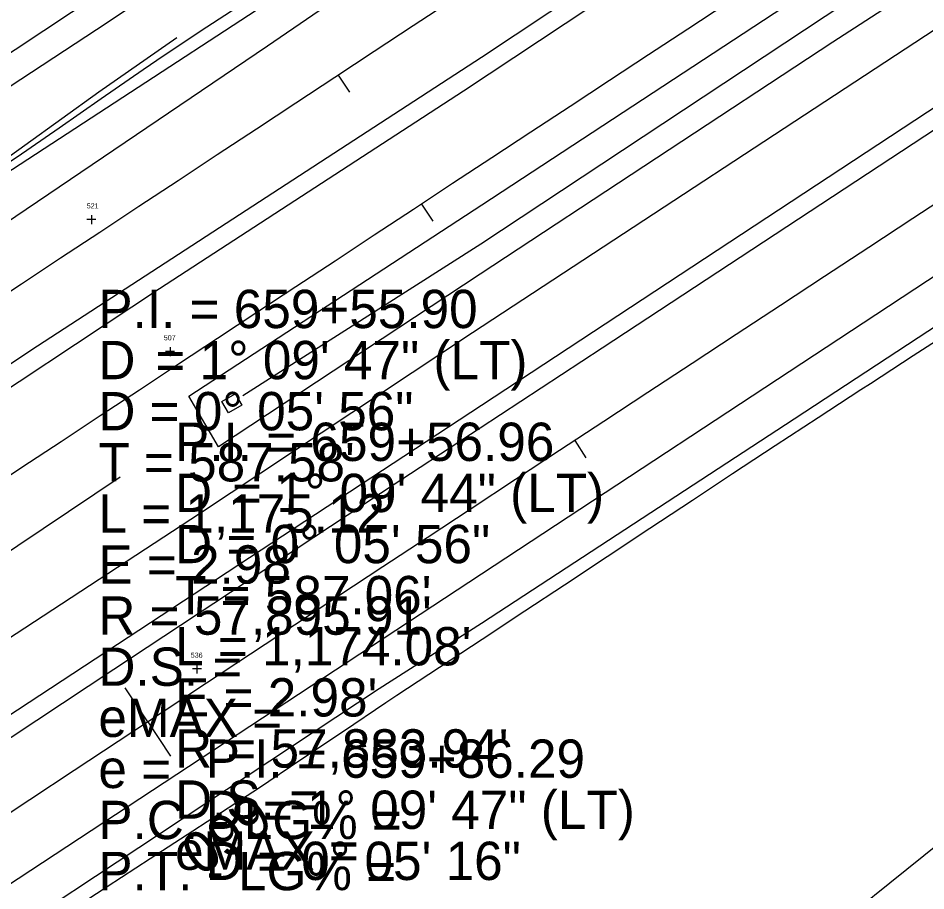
# Model space of a CAD drawing. Extents: x 1901471 to 1963503, y 756461 to 799997.
# Drawn here: x 1916709.3 to 1916886.8, y 764904.9 to 765075.7 of the extents above; entities that cross this region are included whole.
import ezdxf

# ---------------------------------------------------------------- set-up
doc = ezdxf.new("R2010")
doc.units = 0
for name, color, linetype in [('Default', 7, 'Continuous'), ('RD_DTM_BkLn1', 7, 'Continuous'), ('RD_EX_DR_ErosCtrl', 7, 'Continuous'), ('RD_EX_DR_Inlet', 7, 'Continuous'), ('RD_EX_Fence_Other', 7, 'Continuous'), ('RD_EX_GuardRail', 7, 'Continuous'), ('RD_EX_H2O', 7, 'Continuous'), ('RD_EX_Road', 7, 'Continuous'), ('RD_EX_VEG', 7, 'Continuous'), ('RD_HC_Cl', 7, 'Continuous'), ('RD_HC_Data', 7, 'Continuous'), ('RD_HC_Data_Tic', 7, 'Continuous'), ('RD_HC_TX_Sta50', 7, 'Continuous')]:
    doc.layers.add(name, color=color, linetype=linetype)

msp = doc.modelspace()

# ---------------------------------------------------------------- linework, layer by layer
at = {"layer": 'Default'}
for p, q in [((1916723.6276000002, 765037.0992000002), (1916723.6276000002, 765035.3492000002)), ((1916724.5026000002, 765036.2242000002), (1916722.7526000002, 765036.2242000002)), ((1916739.9036000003, 765010.4105000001), (1916738.1536000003, 765010.4105000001)), ((1916739.0286000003, 765011.2855000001), (1916739.0286000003, 765009.5355000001)), ((1916745.1515000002, 764948.3001000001), (1916743.4015000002, 764948.3001000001)), ((1916744.2765000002, 764949.1751000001), (1916744.2765000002, 764947.4251000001))]:
    msp.add_line(p, q, dxfattribs=at)
at = {"layer": 'RD_DTM_BkLn1'}
for points in [[(1916684.0417776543, 765031.9867616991), (1916692.384836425, 765037.4975540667), (1916700.7278951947, 765043.0083464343), (1916709.0983214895, 765048.5372157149), (1916717.3235331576, 765054.2226557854), (1916725.5487448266, 765059.9080958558), (1916733.7739564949, 765065.5935359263), (1916737.8684454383, 765068.423733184), (1916746.2110748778, 765073.9342419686), (1916754.553704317, 765079.4447507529), (1916762.8963337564, 765084.9552595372), (1916769.8116957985, 765089.5230236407)], [(1916756.3112790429, 764925.005669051), (1916764.6165575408, 764930.5728360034), (1916772.9218360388, 764936.1400029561), (1916781.2271145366, 764941.7071699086), (1916783.367330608, 764943.1417925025), (1916791.7101004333, 764948.6523940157), (1916800.052870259, 764954.1629955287), (1916808.3956400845, 764959.6735970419), (1916816.1406750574, 764964.7893802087), (1916824.478940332, 764970.3082059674), (1916832.8172056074, 764975.827031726), (1916841.155470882, 764981.345857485), (1916849.016689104, 764986.5489413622), (1916857.384705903, 764992.0213784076), (1916865.752722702, 764997.493815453), (1916874.120739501, 765002.9662524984), (1916875.9683714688, 765004.1745495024), (1916884.3550358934, 765009.6166364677), (1916892.741700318, 765015.0587234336)], [(1916708.5128141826, 764893.7486122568), (1916716.8498088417, 764899.2672688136), (1916718.373893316, 764900.2761334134), (1916726.7503304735, 764905.7363251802), (1916735.1267676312, 764911.1965169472), (1916743.5032047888, 764916.656708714), (1916751.8796419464, 764922.116900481), (1916756.3112790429, 764925.005669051)]]:
    msp.add_lwpolyline(points, dxfattribs=at)
at = {"layer": 'RD_EX_DR_ErosCtrl'}
msp.add_lwpolyline([(1916800.0000000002, 765039.1500000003), (1916931.9400000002, 765125.7400000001), (1917044.8400000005, 765199.0300000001), (1917050.4100000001, 765188.6500000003), (1916868.6600000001, 765070.9400000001), (1916799.6700000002, 765025.5300000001), (1916748.4600000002, 764991.7500000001), (1916742.6800000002, 765001.6700000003)], close=True, dxfattribs=at)
msp.add_lwpolyline([(1916799.7000000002, 765123.4700000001), (1916724.6300000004, 765073.3400000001), (1916682.4600000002, 765045.7200000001), (1916625.7900000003, 765009.05), (1916568.6900000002, 764972.6000000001), (1916543.5500000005, 764959.9600000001), (1916530.5600000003, 764953.7000000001), (1916500.5900000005, 764942.4700000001), (1916432.8100000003, 764910.9300000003), (1916367.8700000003, 764882.2100000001), (1916314.2600000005, 764858.9500000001), (1916300.9600000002, 764852.9000000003)], dxfattribs=at)
at = {"layer": 'RD_EX_DR_Inlet'}
msp.add_lwpolyline([(1916750.4200000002, 764998.4000000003), (1916749.14, 765000.6100000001), (1916751.7800000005, 765002.1300000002), (1916753.0500000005, 764999.9200000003)], close=True, dxfattribs=at)
at = {"layer": 'RD_EX_Fence_Other'}
msp.add_lwpolyline([(1916134.6300000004, 764571.6400000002), (1916199.0700000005, 764614.9000000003), (1916251.5600000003, 764650.1100000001), (1916318.4900000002, 764695.3700000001), (1916393.5600000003, 764745.2800000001), (1916466.3000000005, 764794.3600000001), (1916531.2400000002, 764837.9500000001), (1916600.1700000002, 764883.5400000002), (1916678.0600000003, 764935.1100000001), (1916744.9900000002, 764978.8700000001), (1916798.14, 765014.1700000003), (1916892.6000000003, 765076.08), (1916972.1600000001, 765128.06), (1917012.5500000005, 765153.9900000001), (1917039.2000000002, 765171.83), (1917084.9300000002, 765201.7700000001)], dxfattribs=at)
at = {"layer": 'RD_EX_GuardRail'}
msp.add_lwpolyline([(1916167.6900000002, 764687.2700000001), (1916191.4400000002, 764703.55), (1916217.1900000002, 764721.07), (1916233.4600000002, 764731.7000000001), (1916257.3800000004, 764748.1400000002), (1916280.3000000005, 764763.3400000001), (1916318.5000000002, 764789.08), (1916350.39, 764810.6700000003), (1916370.8100000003, 764824.2100000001), (1916407.0200000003, 764848.6200000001), (1916447.0500000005, 764875.2800000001), (1916478.9400000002, 764896.3700000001), (1916506.3400000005, 764914.9700000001), (1916525.4400000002, 764927.3500000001), (1916543.0400000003, 764939.3), (1916563.4700000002, 764952.7600000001), (1916588.0500000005, 764969.0300000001), (1916601.6700000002, 764977.9200000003), (1916636.7100000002, 765001.1700000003), (1916670.2600000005, 765023.4200000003), (1916697.8300000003, 765042.1100000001), (1916703.3100000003, 765045.6000000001), (1916725.0700000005, 765061.2100000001), (1916740.3500000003, 765071.8400000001)], dxfattribs=at)
at = {"layer": 'RD_EX_H2O'}
for points in [[(1917267.0900000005, 765334.6400000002), (1917107.7100000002, 765232.55), (1917047.9100000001, 765193.3), (1916930.4200000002, 765117.9000000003), (1916799.7800000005, 765031.4200000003), (1916753.2500000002, 765001.7800000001)], [(1916312.3200000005, 764860.82), (1916374.2100000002, 764887.2800000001), (1916454.9200000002, 764922.7800000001), (1916523.0800000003, 764954.9100000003), (1916559.5600000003, 764973.2200000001), (1916622.7800000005, 765012.5400000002), (1916697.6700000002, 765062.2400000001), (1916769.4200000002, 765109.8500000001), (1916800.0600000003, 765129.3500000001), (1916948.9000000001, 765227.5100000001), (1916996.4900000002, 765260.2900000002)], [(1916729.2800000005, 764985.82), (1916619.0400000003, 764911.8500000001), (1916527.2800000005, 764852.1100000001), (1916438.6700000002, 764791.6700000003), (1916363.3100000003, 764742.7400000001), (1916334.7000000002, 764722.8500000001), (1916314.9900000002, 764708.7200000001)]]:
    msp.add_lwpolyline(points, dxfattribs=at)
at = {"layer": 'RD_EX_Road'}
for points in [[(1917927.8700000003, 765874.3600000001), (1917815.7200000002, 765798.1900000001), (1917496.4700000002, 765582.08), (1917281.5800000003, 765436.3900000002), (1917177.8300000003, 765367.4000000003), (1917104.0200000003, 765316.8600000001), (1917016.2600000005, 765258.32), (1916800.1500000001, 765109.6600000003), (1916769.4400000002, 765089.0100000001), (1916762.0500000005, 765081.2600000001), (1916688.0500000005, 765032.9100000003), (1916621.2500000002, 764988.7200000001), (1916539.3200000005, 764934.56), (1916453.6900000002, 764877.4400000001), (1916368.2500000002, 764820.5100000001), (1916289.8200000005, 764767.2700000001), (1916190.5400000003, 764700.3800000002), (1916051.4000000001, 764607.0000000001)], [(1917885.0200000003, 765834.3800000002), (1917833.9700000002, 765799.9300000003), (1917742.9300000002, 765738.32), (1917651.6800000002, 765676.5000000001), (1917566.1800000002, 765618.3700000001), (1917494.2100000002, 765569.4700000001), (1917423.4700000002, 765521.1800000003), (1917314.1900000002, 765447.4700000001), (1917247.9600000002, 765402.8700000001), (1917145.2300000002, 765334.4900000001), (1917055.2200000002, 765272.8700000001), (1916955.5700000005, 765204.7000000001), (1916864.3300000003, 765142.4700000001), (1916799.9400000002, 765098.8700000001), (1916758.0600000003, 765070.1600000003), (1916695.9000000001, 765028.1200000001), (1916632.1100000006, 764985.7200000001), (1916578.1900000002, 764949.7800000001), (1916513.64, 764907.1200000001), (1916455.1700000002, 764867.8900000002), (1916385.0500000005, 764820.9300000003), (1916323.7900000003, 764779.9200000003), (1916263.2900000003, 764739.2900000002), (1916172.1600000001, 764677.9100000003)], [(1916110.9000000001, 764608.9300000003), (1916192.9200000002, 764663.8600000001), (1916281.0100000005, 764723.4700000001), (1916411.8800000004, 764810.6800000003), (1916531.8700000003, 764891.05), (1916608.8200000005, 764942.31), (1916713.1200000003, 765011.5400000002), (1916799.9400000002, 765067.9900000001), (1916886.4700000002, 765125.55), (1916964.39, 765176.0900000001), (1917049.2700000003, 765231.1500000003), (1917118.3700000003, 765276.1500000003), (1917204.2800000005, 765331.82), (1917277.4800000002, 765379.2900000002), (1917360.1200000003, 765432.9100000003), (1917439.6700000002, 765484.07), (1917498.3100000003, 765522.5100000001), (1917549.5700000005, 765555.5200000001), (1917628.5100000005, 765606.07), (1917717.5000000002, 765663.58), (1917792.14, 765712.07), (1917872.1000000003, 765763.4400000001)], [(1916154.7400000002, 764633.3900000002), (1916196.0800000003, 764661.6300000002), (1916324.7000000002, 764748.6400000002), (1916419.0000000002, 764811.4700000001), (1916491.3400000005, 764859.1700000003), (1916561.0900000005, 764905.7700000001), (1916649.1200000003, 764964.5400000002), (1916736.9600000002, 765022.7700000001), (1916796.3800000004, 765061.4300000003), (1916851.0000000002, 765097.6700000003), (1916904.9200000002, 765132.6300000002), (1916961.9200000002, 765170.7600000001), (1917044.7600000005, 765223.9700000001), (1917125.3400000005, 765276.3600000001), (1917220.0700000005, 765337.56), (1917301.4700000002, 765390.3600000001), (1917405.2200000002, 765457.9200000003), (1917495.4400000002, 765515.8500000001), (1917533.9900000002, 765541.3800000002), (1917670.14, 765628.83), (1917768.9700000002, 765692.9000000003), (1917871.4900000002, 765758.82)], [(1916059.5700000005, 764506.4300000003), (1916189.89, 764593.4600000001), (1916307.7100000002, 764673.31), (1916486.1600000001, 764791.9100000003), (1916655.2300000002, 764904.8800000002), (1916799.9200000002, 764999.8900000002), (1916933.2200000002, 765087.7200000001), (1917040.4600000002, 765158.1500000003), (1917127.39, 765214.4400000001), (1917233.8100000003, 765282.82), (1917344.9400000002, 765354.4800000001), (1917435.7800000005, 765413.4300000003), (1917510.0000000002, 765461.1000000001), (1917596.9400000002, 765517.1800000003), (1917688.8000000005, 765576.5400000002), (1917776.7600000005, 765633.2300000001), (1917862.2600000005, 765688.7000000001), (1917948.1700000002, 765744.1600000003)], [(1917920.7000000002, 765683.7800000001), (1917827.6100000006, 765623.6000000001), (1917724.2700000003, 765556.8600000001), (1917629.7400000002, 765496.06), (1917551.6200000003, 765445.1100000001), (1917440.4900000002, 765373.4500000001), (1917340.4300000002, 765309.3700000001), (1917237.9100000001, 765243.0400000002), (1917140.5200000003, 765180.4000000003), (1917052.7600000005, 765122.8900000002), (1916953.7200000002, 765057.9900000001), (1916861.0400000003, 764997.2000000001), (1916799.9200000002, 764957.2300000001), (1916779.9200000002, 764944.4200000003), (1916660.2300000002, 764865.2000000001), (1916531.4700000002, 764780.5000000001), (1915851.1300000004, 764323.2900000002)], [(1917892.4000000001, 765675.58), (1917788.2400000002, 765608.0100000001), (1917693.3100000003, 765546.6000000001), (1917618.2600000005, 765498.5200000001), (1917523.1200000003, 765436.9100000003), (1917422.6500000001, 765372.2200000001), (1917337.7700000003, 765317.7800000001), (1917248.1600000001, 765259.6500000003), (1917148.1000000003, 765194.9600000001), (1917050.9100000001, 765131.5000000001), (1916953.3100000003, 765067.83), (1916877.0400000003, 765017.6000000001), (1916799.9400000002, 764966.8600000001), (1916704.5100000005, 764904.0900000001), (1916609.3300000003, 764840.6700000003), (1916504.7900000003, 764770.9400000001), (1916395.9400000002, 764698.4100000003), (1916297.7200000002, 764632.7200000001), (1916137.4800000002, 764524.7600000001)], [(1916149.3800000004, 764561.5900000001), (1916214.9400000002, 764605.7600000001), (1916273.6700000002, 764645.2500000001), (1916332.6500000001, 764684.8700000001), (1916393.9100000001, 764726.1300000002), (1916470.6100000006, 764776.8800000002), (1916523.0100000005, 764812.32), (1916589.3300000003, 764856.2400000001), (1916652.8700000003, 764898.5200000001), (1916728.0500000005, 764948.2600000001), (1916780.2000000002, 764982.6800000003), (1916799.6900000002, 764995.4700000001), (1916823.5200000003, 765011.1400000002), (1916906.9700000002, 765065.9900000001), (1916985.7100000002, 765117.7600000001), (1917079.6200000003, 765178.7600000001)]]:
    msp.add_lwpolyline(points, dxfattribs=at)
at = {"layer": 'RD_EX_VEG'}
msp.add_lwpolyline([(1916697.4300000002, 764822.0900000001), (1916717.3600000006, 764830.2100000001), (1916737.8500000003, 764834.2700000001), (1916750.7600000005, 764838.7900000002), (1916772.7200000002, 764858.3500000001), (1916783.9800000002, 764872.0100000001), (1916793.0200000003, 764875.9800000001), (1916799.4800000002, 764875.9800000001), (1916823.9700000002, 764872.8900000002), (1916853.8400000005, 764885.55), (1916899.4100000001, 764922.2500000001), (1916965.7300000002, 764967.06), (1917011.0400000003, 764996.8), (1917059.14, 765027.1800000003), (1917101.1600000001, 765055.5300000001)], dxfattribs=at)
at = {"layer": 'RD_HC_Cl'}
for centre, radius, start, end in [((1948618.927154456, 716714.6838111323), 57895.907900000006, 122.84589019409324, 124.00882459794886), ((1948627.813986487, 716698.9149995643), 57883.94070000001, 122.84637793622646, 124.00852866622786), ((1952673.9465588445, 710531.7599155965), 65204.77830000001, 122.85416067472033, 124.0171003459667)]:
    msp.add_arc(centre, radius, start, end, dxfattribs=at)
at = {"layer": 'RD_HC_Data_Tic'}
for p, q in [((1916771.9178279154, 765064.4940333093), (1916774.1181222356, 765061.1535685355)), ((1916788.2039341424, 765039.2689771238), (1916790.4041720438, 765035.9284751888)), ((1916818.1480355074, 764992.9830510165), (1916820.3476165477, 764989.6421165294)), ((1916734.6668728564, 764937.9294996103), (1916730.2574684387, 764944.6046140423)), ((1916734.6668728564, 764937.9294996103), (1916739.0762772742, 764931.2543851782))]:
    msp.add_line(p, q, dxfattribs=at)

# ---------------------------------------------------------------- texts
at = {"layer": 'Default'}
for s, p in [('521', (1916722.7299622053, 765038.4242000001)), ('507', (1916737.8081275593, 765012.6105000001)), ('536', (1916743.0717755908, 764950.5001))]:
    msp.add_text(s, height=1.0000000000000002, dxfattribs=at).set_placement(p)
at = {"layer": 'RD_HC_Data'}
for s, p in [('P.I. = 659+55.90', (1916725.0000000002, 765015.0000000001)), ('D', (1916725.0000000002, 765005.0000000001)), ('    = 1%%d 09\' 47" (LT)', (1916725.0000000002, 765005.0000000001)), ('D = 0%%d 05\' 56"', (1916725.0000000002, 764995.0000000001)), ('P.I. = 659+56.96', (1916740.0000000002, 764989.0000000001)), ("T = 587.58'", (1916725.0000000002, 764985.0000000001)), ('D', (1916740.0000000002, 764979.0000000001)), ('    = 1%%d 09\' 44" (LT)', (1916740.0000000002, 764979.0000000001)), ("L = 1,175.12'", (1916725.0000000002, 764975.0000000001)), ('D = 0%%d 05\' 56"', (1916740.0000000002, 764969.0000000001)), ("E = 2.98'", (1916725.0000000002, 764965.0000000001)), ("T = 587.06'", (1916740.0000000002, 764959.0000000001)), ("R = 57,895.91'", (1916725.0000000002, 764955.0000000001)), ("L = 1,174.08'", (1916740.0000000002, 764949.0000000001)), ('D.S. = ', (1916725.0000000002, 764945.0000000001)), ("E = 2.98'", (1916740.0000000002, 764939.0000000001)), ('eMAX = ', (1916725.0000000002, 764935.0000000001)), ("R = 57,883.94'", (1916740.0000000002, 764929.0000000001)), ('P.I. = 659+86.29', (1916746.0000000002, 764927.0000000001)), ('e = ', (1916725.0000000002, 764925.0000000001)), ('D.S. = ', (1916740.0000000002, 764919.0000000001)), ('D', (1916746.0000000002, 764917.0000000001)), ('    = 1%%d 09\' 47" (LT)', (1916746.0000000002, 764917.0000000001)), ('P.C. - LG% = ', (1916725.0000000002, 764915.0000000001)), ('eMAX = ', (1916740.0000000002, 764909.0000000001)), ('D = 0%%d 05\' 16"', (1916746.0000000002, 764907.0000000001)), ('P.T. - LG% = ', (1916725.0000000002, 764905.0000000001))]:
    msp.add_text(s, height=7.500000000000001, dxfattribs=at).set_placement(p)
at = {"layer": 'RD_HC_TX_Sta50'}
msp.add_text('660', height=8.000000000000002, rotation=213.47102444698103, dxfattribs=at).set_placement((1916755.3028986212, 764924.1416490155))

doc.saveas('drawing.dxf')
